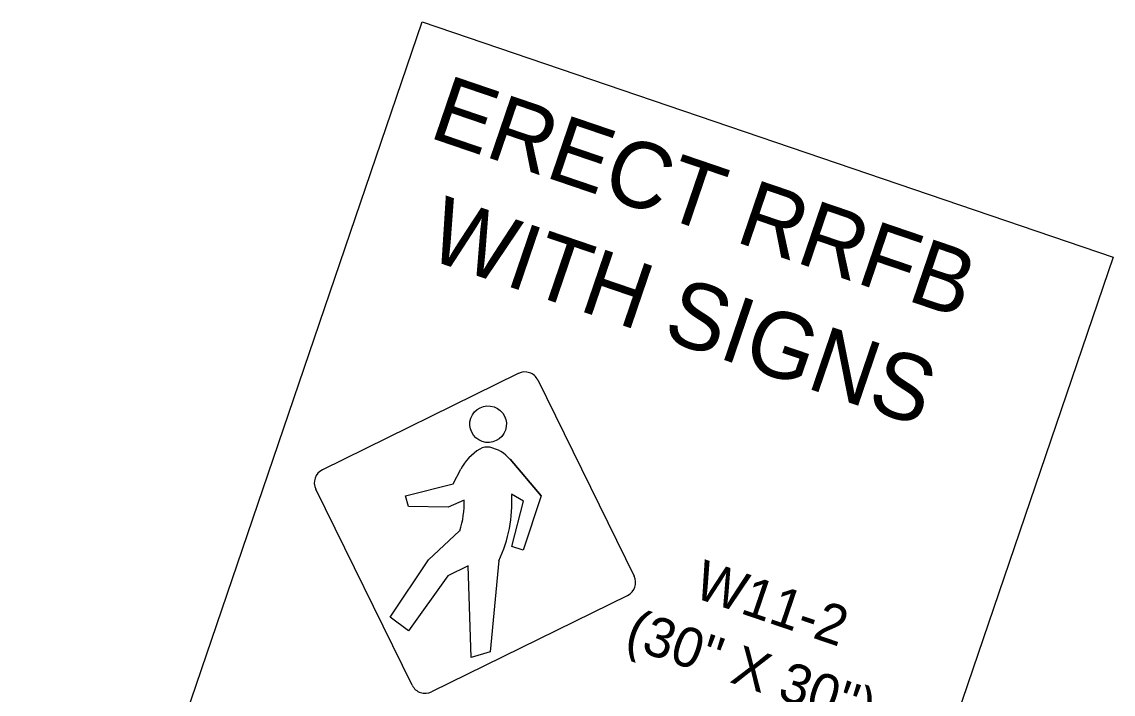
# Model space of a CAD drawing. Extents: x 902965 to 1126554, y 597041 to 686906.
# Drawn here: x 929056.3 to 929180.4, y 686829.2 to 686905.6 of the extents above; entities that cross this region are included whole.
import ezdxf

# ---------------------------------------------------------------- set-up
doc = ezdxf.new("R2010")
doc.units = 0
for name, color, linetype in [('Default', 7, 'Continuous'), ('Prop DSN Text', 7, 'Continuous'), ('WS W11-2 CELL', 7, 'Continuous')]:
    doc.layers.add(name, color=color, linetype=linetype)

msp = doc.modelspace()

# ---------------------------------------------------------------- linework, layer by layer
at = {"layer": 'Prop DSN Text'}
msp.add_lwpolyline([(929101.83, 686905.65), (929180.36, 686878.89), (929134.85, 686745.34), (929056.32, 686772.09)], close=True, dxfattribs=at)
at = {"layer": 'WS W11-2 CELL'}
for p, q in [((929111.81, 686855.93), (929115.33, 686851.78)), ((929115.33, 686851.78), (929111.81, 686855.93)), ((929111.81, 686855.93), (929115.33, 686851.78)), ((929105.33, 686853.15), (929106.21, 686854.8)), ((929099.92, 686851.76), (929105.33, 686853.15)), ((929100.28, 686850.55), (929099.92, 686851.76)), ((929106.61, 686851.3), (929104.79, 686850.5)), ((929113.33, 686851.17), (929111.99, 686851.95)), ((929112.03, 686846.03), (929113.33, 686851.17)), ((929115.33, 686851.78), (929113.29, 686845.6)), ((929104.79, 686850.5), (929100.28, 686850.55)), ((929102.53, 686844.52), (929106.08, 686847.8)), ((929113.29, 686845.6), (929112.03, 686846.03)), ((929098.18, 686837.98), (929102.53, 686844.52)), ((929107.04, 686843.82), (929104.73, 686842.68)), ((929107.41, 686833.42), (929107.04, 686843.82)), ((929110.54, 686844.41), (929109.55, 686834.04)), ((929104.73, 686842.68), (929100.28, 686836.43)), ((929125.18, 686840.46), (929102.88, 686829.5)), ((929125.18, 686840.46), (929102.88, 686829.5)), ((929100.28, 686836.43), (929098.18, 686837.98)), ((929109.55, 686834.04), (929107.41, 686833.42))]:
    msp.add_line(p, q, dxfattribs=at)
for points in [[(929090.47, 686854.73), (929112.77, 686865.7)], [(929114.96, 686864.95), (929125.93, 686842.65)], [(929100.69, 686830.24), (929089.72, 686852.54)]]:
    msp.add_lwpolyline(points, dxfattribs=at)
for centre, major_axis, start_param, end_param in [((929113.49, 686864.22), (0.53, 1.55), 6.283072, 7.068583), ((929113.49, 686864.22), (0.53, 1.55), 5.49756, 6.283072), ((929109.2, 686855.75), (-0.51, -1.49), 3.261682, 4.017186), ((929108.68, 686853.28), (1.32, 3.88), 5.744678, 6.403274), ((929111.52, 686851.94), (-1.95, -5.71), 4.017186, 4.547553), ((929091.2, 686853.26), (0.53, 1.55), 0.785398, 2.356194), ((929096.47, 686851.02), (3.27, 9.6), 4.717416, 5.067864), ((929096.47, 686851.02), (5.02, 14.72), 4.60131, 5.100443), ((929124.45, 686841.93), (0.53, 1.55), 3.926991, 5.497787), ((929102.16, 686830.97), (-0.53, -1.55), 5.497787, 6.283185), ((929102.16, 686830.97), (-0.53, -1.55), 6.283185, 7.068583)]:
    msp.add_ellipse(centre, major_axis=major_axis, ratio=0.999996, start_param=start_param, end_param=end_param, dxfattribs=at)
msp.add_ellipse((929109.32, 686859.92), major_axis=(0.67, 1.97), ratio=0.999996, dxfattribs=at)

# ---------------------------------------------------------------- texts
at = {"layer": 'Default'}
for s, p in [('ERECT RRFB ', (929102.42, 686892.57)), ('WITH SIGNS', (929102.05, 686878.83))]:
    msp.add_text(s, height=7.5, rotation=341.1837, dxfattribs=at).set_placement(p)
at = {"layer": 'WS W11-2 CELL'}
for s, p in [('W11-2', (929132.46, 686840.32)), ("(30'' X 30'')", (929124.67, 686834.71))]:
    msp.add_text(s, height=4.5, rotation=341.1837, dxfattribs=at).set_placement(p)

doc.saveas('drawing.dxf')
